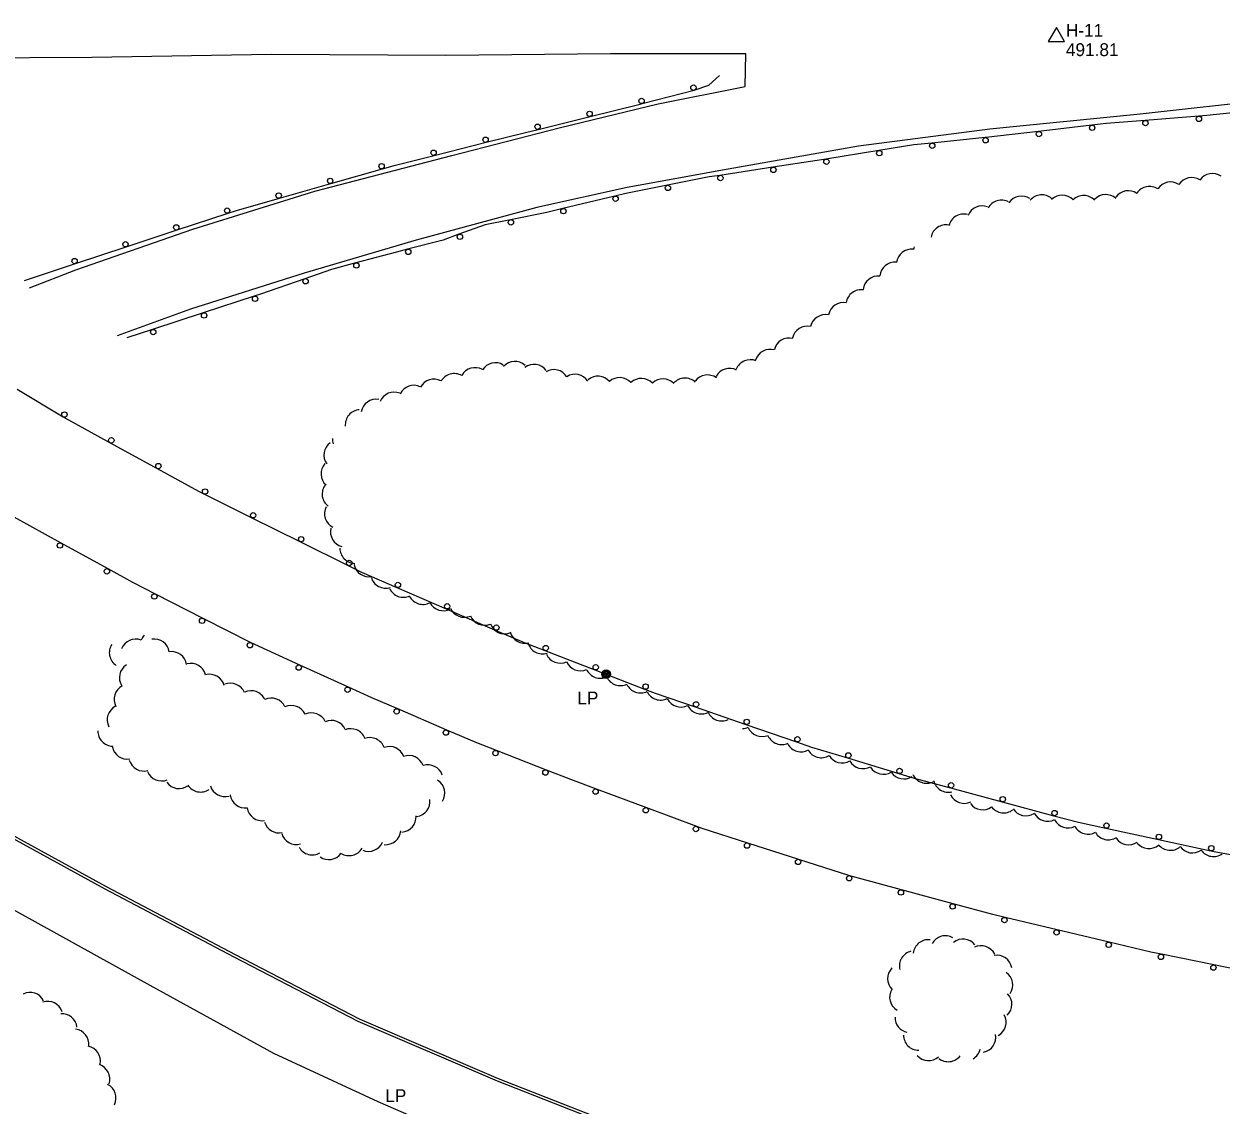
# Model space of a CAD drawing. Extents: x 2402803 to 2427059, y 6985292 to 6997652.
# Drawn here: x 2417273.9 to 2417720.3, y 6990965.6 to 6991368.8 of the extents above; entities that cross this region are included whole.
import ezdxf

# ---------------------------------------------------------------- set-up
doc = ezdxf.new("R2010")
doc.units = 0
for name, color, linetype in [('p_control ground ctrl', 7, 'Continuous'), ('p_road - paved curb', 7, 'Continuous'), ('p_road guard rails', 7, 'Continuous'), ('p_utility manhole', 7, 'Continuous'), ('p_veg woods', 7, 'Continuous'), ('V7 LEVEL 31', 7, 'Continuous')]:
    doc.layers.add(name, color=color, linetype=linetype)

msp = doc.modelspace()

# ---------------------------------------------------------------- linework, layer by layer
at = {"layer": 'p_control ground ctrl'}
for p, q in [((2417658.86, 6991367.48), (2417655.86, 6991362.28)), ((2417661.86, 6991362.28), (2417658.86, 6991367.48)), ((2417655.86, 6991362.28), (2417661.86, 6991362.28)), ((2417658.86, 6991364), (2417658.86, 6991364.04))]:
    msp.add_line(p, q, dxfattribs=at)
at = {"layer": 'p_road - paved curb'}
for points in [[(2417275.88, 6991270.34), (2417293.26, 6991277.04), (2417336.91, 6991292.21), (2417382.32, 6991306.42), (2417433.4, 6991319.71), (2417473.97, 6991330.18), (2417510.41, 6991338.96), (2417542.82, 6991345.45), (2417543.12, 6991357.69), (2417492.59, 6991357.71), (2417431.19, 6991357.03), (2417366.14, 6991357.43), (2417299.23, 6991356.3), (2417252.69, 6991356.08), (2417188.74, 6991355.17), (2417152.25, 6991354.93)], [(2418072.8, 6991352.05), (2418071.7, 6991352.04), (2418029.59, 6991351.13), (2417976.83, 6991352.21), (2417927.51, 6991351.28), (2417887.18, 6991349.28), (2417844.29, 6991346.03), (2417797.06, 6991344.87), (2417739.41, 6991340.6), (2417690.1, 6991335.1), (2417634, 6991329.56), (2417585.11, 6991323.22), (2417536.45, 6991314.6), (2417498.86, 6991307.78), (2417465.16, 6991300.29), (2417420.17, 6991288.13), (2417378.32, 6991275.91), (2417336.02, 6991262.39), (2417308.65, 6991252.45)], [(2417102.44, 6991155.35), (2417147.44, 6991131.02), (2417202.6, 6991101.41), (2417246.57, 6991077.7), (2417304.09, 6991046.19), (2417352.2, 6991020.88), (2417398.41, 6990996.87), (2417450.39, 6990974.63), (2417510.07, 6990951.19), (2417573, 6990930.87), (2417630.32, 6990916.28), (2417690.09, 6990903.9), (2417747.18, 6990895.52), (2417798.03, 6990890.45), (2417854.87, 6990887.91), (2417913.31, 6990887.8), (2417972.37, 6990890.82), (2418042.27, 6990897.81), (2418103.6, 6990905.73), (2418162.42, 6990914.12), (2418202.32, 6990920.88), (2418234.72, 6990926.56)], [(2417102.92, 6991156.23), (2417147.91, 6991131.9), (2417203.07, 6991102.29), (2417247.05, 6991078.58), (2417304.56, 6991047.07), (2417352.66, 6991021.77), (2417398.84, 6990997.77), (2417450.77, 6990975.56), (2417510.41, 6990952.13), (2417573.28, 6990931.83), (2417630.54, 6990917.25), (2417690.26, 6990904.89), (2417747.3, 6990896.51), (2417798.1, 6990891.45), (2417854.89, 6990888.91), (2417913.29, 6990888.8), (2417972.29, 6990891.82), (2418042.16, 6990898.8), (2418103.47, 6990906.72), (2418162.27, 6990915.11), (2418202.15, 6990921.87), (2418234.55, 6990927.54)], [(2417663.11, 6990894.16), (2417661.52, 6990884.87), (2417622.52, 6990891.62), (2417574.86, 6990904.07), (2417532.81, 6990916.94), (2417488.56, 6990932.5), (2417444.88, 6990949.85), (2417405.95, 6990966.76), (2417367, 6990984.85), (2417320.93, 6991010.25), (2417251.16, 6991048.68), (2417181.38, 6991084.69), (2417135.29, 6991109.88), (2417079.87, 6991140.57)]]:
    msp.add_lwpolyline(points, dxfattribs=at)
at = {"layer": 'p_road guard rails'}
for p, q in [((2417504.43, 6991339.11), (2417523.79, 6991344.06)), ((2417465.66, 6991329.49), (2417485.05, 6991334.3)), ((2417711.95, 6991334.39), (2417692.02, 6991332.83)), ((2417672.1, 6991331.06), (2417652.23, 6991328.74)), ((2417426.88, 6991319.79), (2417446.27, 6991324.65)), ((2417632.37, 6991326.41), (2417612.47, 6991324.38)), ((2417592.68, 6991321.59), (2417572.95, 6991318.42)), ((2417388.33, 6991309.31), (2417407.53, 6991314.78)), ((2417553.19, 6991315.37), (2417533.43, 6991312.34)), ((2417369.13, 6991303.84), (2417388.33, 6991309.31)), ((2417494.27, 6991304.59), (2417474.81, 6991299.95)), ((2417331, 6991291.96), (2417349.97, 6991298.24)), ((2417312.04, 6991285.69), (2417331, 6991291.96)), ((2417293.07, 6991279.41), (2417312.04, 6991285.69)), ((2417274.11, 6991273.14), (2417293.07, 6991279.41)), ((2417359.73, 6991267.25), (2417340.74, 6991261.04)), ((2417340.74, 6991261.04), (2417321.76, 6991254.83)), ((2417321.76, 6991254.83), (2417312.27, 6991251.73)), ((2417271.34, 6991232.6), (2417288.46, 6991222.27)), ((2417305.98, 6991212.63), (2417323.51, 6991203.03)), ((2417340.99, 6991193.55), (2417358.9, 6991184.66)), ((2417287.75, 6991175.17), (2417270.23, 6991184.8)), ((2417358.9, 6991184.66), (2417376.81, 6991175.77)), ((2417305.28, 6991165.54), (2417287.75, 6991175.17)), ((2417376.81, 6991175.77), (2417394.72, 6991166.88)), ((2417340.76, 6991147.09), (2417322.95, 6991156.17)), ((2417412.94, 6991158.66), (2417431.29, 6991150.71)), ((2417431.29, 6991150.71), (2417449.64, 6991142.75)), ((2417358.58, 6991138), (2417340.76, 6991147.09)), ((2417468.1, 6991135.12), (2417486.72, 6991127.94)), ((2417394.96, 6991121.43), (2417376.75, 6991129.68)), ((2417486.72, 6991127.94), (2417505.34, 6991120.76)), ((2417431.61, 6991105.44), (2417413.24, 6991113.35)), ((2417524.18, 6991114.1), (2417543.07, 6991107.59)), ((2417543.07, 6991107.59), (2417561.97, 6991101.08)), ((2417468.71, 6991090.55), (2417450.08, 6991097.79)), ((2417581.01, 6991095.06), (2417600.1, 6991089.25)), ((2417506.1, 6991076.47), (2417487.39, 6991083.45)), ((2417619.34, 6991083.89), (2417638.63, 6991078.71)), ((2417524.81, 6991069.5), (2417506.1, 6991076.47)), ((2417638.63, 6991078.71), (2417657.93, 6991073.53)), ((2417677.35, 6991068.86), (2417696.9, 6991064.65)), ((2417562.86, 6991057.23), (2417543.82, 6991063.32)), ((2417696.9, 6991064.65), (2417716.44, 6991060.44)), ((2417581.9, 6991051.14), (2417562.86, 6991057.23)), ((2417620.43, 6991040.64), (2417601.15, 6991045.85)), ((2417659.18, 6991030.96), (2417639.74, 6991035.57)), ((2417678.61, 6991026.34), (2417659.18, 6991030.96)), ((2417717.64, 6991017.85), (2417698.07, 6991021.85)), ((2417737.21, 6991013.86), (2417717.64, 6991017.85))]:
    msp.add_line(p, q, dxfattribs=at)
for points in [[(2417523.79, 6991344.06), (2417523.82, 6991344.07), (2417529.22, 6991345.97), (2417533.26, 6991349.51)], [(2417485.05, 6991334.3), (2417503.65, 6991338.91), (2417504.43, 6991339.11)], [(2417731.85, 6991336.39), (2417714.95, 6991334.63), (2417711.95, 6991334.39)], [(2417446.27, 6991324.65), (2417460.95, 6991328.32), (2417465.66, 6991329.49)], [(2417692.02, 6991332.83), (2417677.4, 6991331.68), (2417672.1, 6991331.06)], [(2417612.47, 6991324.38), (2417605.66, 6991323.68), (2417592.68, 6991321.59)], [(2417652.23, 6991328.74), (2417632.53, 6991326.43), (2417632.37, 6991326.41)], [(2417407.53, 6991314.78), (2417412.37, 6991316.16), (2417426.88, 6991319.79)], [(2417572.95, 6991318.42), (2417569.72, 6991317.9), (2417553.19, 6991315.37)], [(2417533.43, 6991312.34), (2417529.45, 6991311.73), (2417513.82, 6991308.63)], [(2417513.82, 6991308.63), (2417498.28, 6991305.54), (2417494.27, 6991304.59)], [(2417349.97, 6991298.24), (2417353.09, 6991299.27), (2417369.13, 6991303.84)], [(2417474.81, 6991299.95), (2417468.87, 6991298.54), (2417455.26, 6991295.79)], [(2417455.26, 6991295.79), (2417445.85, 6991293.89), (2417436.09, 6991290.34)], [(2417436.09, 6991290.34), (2417430.15, 6991288.18), (2417416.93, 6991284.76)], [(2417416.93, 6991284.76), (2417412.8, 6991283.69), (2417397.6, 6991279.67)], [(2417397.6, 6991279.67), (2417388.52, 6991277.27), (2417378.56, 6991273.78)], [(2417378.56, 6991273.78), (2417362.04, 6991268), (2417359.73, 6991267.25)], [(2417288.46, 6991222.27), (2417289.34, 6991221.74), (2417305.98, 6991212.63)], [(2417323.51, 6991203.03), (2417338.92, 6991194.6), (2417338.92, 6991194.57), (2417340.99, 6991193.55)], [(2417322.95, 6991156.17), (2417314.48, 6991160.49), (2417305.28, 6991165.54)], [(2417394.72, 6991166.88), (2417399.73, 6991164.39), (2417412.94, 6991158.66)], [(2417449.64, 6991142.75), (2417460.35, 6991138.11), (2417468.1, 6991135.12)], [(2417376.75, 6991129.68), (2417359.91, 6991137.32), (2417358.58, 6991138)], [(2417413.24, 6991113.35), (2417403.57, 6991117.52), (2417394.96, 6991121.43)], [(2417505.34, 6991120.76), (2417509.22, 6991119.26), (2417524.18, 6991114.1)], [(2417450.08, 6991097.79), (2417442.74, 6991100.64), (2417431.61, 6991105.44)], [(2417561.97, 6991101.08), (2417567.59, 6991099.14), (2417581.01, 6991095.06)], [(2417487.39, 6991083.45), (2417477.77, 6991087.03), (2417468.71, 6991090.55)], [(2417600.1, 6991089.25), (2417605.84, 6991087.51), (2417619.34, 6991083.89)], [(2417657.93, 6991073.53), (2417667.07, 6991071.08), (2417677.35, 6991068.86)], [(2417543.82, 6991063.32), (2417526.83, 6991068.75), (2417524.81, 6991069.5)], [(2417716.44, 6991060.44), (2417717.74, 6991060.16), (2417736.09, 6991056.79)], [(2417601.15, 6991045.85), (2417583.75, 6991050.55), (2417581.9, 6991051.14)], [(2417639.74, 6991035.57), (2417635.21, 6991036.65), (2417620.43, 6991040.64)], [(2417698.07, 6991021.85), (2417694.12, 6991022.66), (2417678.61, 6991026.34)]]:
    msp.add_lwpolyline(points, dxfattribs=at)
for centre in [(2417523.54, 6991345.03), (2417504.18, 6991340.08), (2417484.81, 6991335.27), (2417712.03, 6991333.4), (2417465.42, 6991330.46), (2417672.21, 6991330.07), (2417692.09, 6991331.83), (2417446.03, 6991325.62), (2417612.57, 6991323.38), (2417632.47, 6991325.42), (2417652.35, 6991327.74), (2417426.63, 6991320.76), (2417592.84, 6991320.61), (2417407.25, 6991315.74), (2417573.11, 6991317.43), (2417388.06, 6991310.27), (2417533.58, 6991311.35), (2417553.35, 6991314.38), (2417514.01, 6991307.65), (2417368.86, 6991304.8), (2417494.5, 6991303.61), (2417349.65, 6991299.19), (2417475.04, 6991298.98), (2417330.69, 6991292.91), (2417455.45, 6991294.81), (2417436.43, 6991289.4), (2417311.73, 6991286.64), (2417417.18, 6991283.79), (2417292.76, 6991280.36), (2417397.86, 6991278.71), (2417378.89, 6991272.84), (2417360.04, 6991266.3), (2417341.06, 6991260.09), (2417322.07, 6991253.88), (2417288.98, 6991223.13), (2417306.46, 6991213.51), (2417323.99, 6991203.91), (2417341.43, 6991194.44), (2417359.34, 6991185.55), (2417377.25, 6991176.66), (2417287.27, 6991174.29), (2417395.16, 6991167.77), (2417304.8, 6991164.66), (2417413.34, 6991159.58), (2417322.49, 6991155.28), (2417431.69, 6991151.62), (2417340.31, 6991146.19), (2417450.04, 6991143.67), (2417358.12, 6991137.11), (2417468.46, 6991136.05), (2417376.34, 6991128.77), (2417487.08, 6991128.87), (2417394.54, 6991120.52), (2417505.7, 6991121.69), (2417524.51, 6991115.05), (2417412.85, 6991112.43), (2417543.4, 6991108.54), (2417431.21, 6991104.52), (2417562.3, 6991102.02), (2417449.72, 6991096.86), (2417581.3, 6991096.02), (2417468.35, 6991089.62), (2417600.39, 6991090.21), (2417487.04, 6991082.51), (2417619.6, 6991084.85), (2417638.89, 6991079.68), (2417505.75, 6991075.54), (2417658.19, 6991074.5), (2417677.56, 6991069.84), (2417524.46, 6991068.57), (2417697.11, 6991065.63), (2417543.51, 6991062.37), (2417716.65, 6991061.42), (2417562.56, 6991056.28), (2417581.6, 6991050.19), (2417600.89, 6991044.88), (2417620.17, 6991039.68), (2417639.51, 6991034.6), (2417658.94, 6991029.99), (2417678.38, 6991025.37), (2417697.87, 6991020.87), (2417717.44, 6991016.87)]:
    msp.add_circle(centre, 1, dxfattribs=at)
at = {"layer": 'p_utility manhole'}
for radius in [1.6, 1.3, 1, 0.539, 0.192]:
    msp.add_circle((2417491.03, 6991126.28), radius, dxfattribs=at)
at = {"layer": 'p_veg woods'}
for centre, start, end in [((2417709.31, 6991305.87), 56.903, 146.903), ((2417717.07, 6991307.33), 55.4286, 145.4286), ((2417685.68, 6991300.96), 55.0374, 145.0374), ((2417693.62, 6991302.56), 56.4386, 146.4386), ((2417701.48, 6991304.22), 56.903, 146.903), ((2417638.42, 6991297.46), 61.9302, 151.9302), ((2417645.9, 6991298.95), 56.5986, 146.5986), ((2417653.39, 6991299.4), 49.2176, 139.2176), ((2417661.05, 6991299.26), 44.2685, 134.2685), ((2417669.06, 6991299.17), 44.4242, 134.4242), ((2417677.29, 6991299.53), 47.8034, 137.8034), ((2417624.3, 6991292.24), 75.3959, 165.3959), ((2417631.22, 6991295.32), 69.1231, 159.1231), ((2417617.69, 6991288.24), 79.2484, 169.2484), ((2417604.84, 6991279.14), 82.9066, 172.9066), ((2417611.2, 6991283.85), 161.5656, 171.6236), ((2417598.64, 6991274.28), 84.5701, 174.5701), ((2417592.45, 6991269.14), 83.9045, 173.9045), ((2417586.05, 6991264), 80.8571, 170.8571), ((2417579.45, 6991259.24), 78.8144, 168.8144), ((2417572.74, 6991254.75), 77.8002, 167.8002), ((2417566.01, 6991250.41), 77.6683, 167.6683), ((2417559.18, 6991246), 75.7371, 165.7371), ((2417552.13, 6991241.81), 72.9008, 162.9008), ((2417442.08, 6991234.98), 61.0508, 151.0507), ((2417449.65, 6991236.81), 58.0793, 148.0793), ((2417456.95, 6991237.28), 48.0542, 138.0542), ((2417464.13, 6991236.15), 37.1526, 127.1526), ((2417471.52, 6991234.24), 31.7164, 121.7164), ((2417536.98, 6991234.71), 62.2601, 152.2601), ((2417544.75, 6991237.94), 68.1706, 158.1706), ((2417426.76, 6991230.7), 62.4444, 152.4444), ((2417434.34, 6991232.76), 60.4241, 150.4241), ((2417479.41, 6991232.5), 32.826, 122.826), ((2417487.91, 6991231.79), 40.3516, 130.3516), ((2417495.98, 6991231.27), 41.5775, 131.5775), ((2417504.07, 6991230.95), 42.9485, 132.9485), ((2417512.15, 6991230.79), 44.1086, 134.1086), ((2417520.37, 6991231.07), 47.3426, 137.3426), ((2417528.72, 6991232.26), 53.4981, 143.4981), ((2417411.91, 6991225.84), 67.8133, 157.8133), ((2417419.26, 6991228.4), 64.7073, 154.7073), ((2417405.23, 6991223.19), 80.2793, 170.2793), ((2417399.33, 6991219.26), 94.1613, 184.1613), ((2417394.58, 6991213.94), 177.07, 197.2145), ((2417391.38, 6991208.02), 125.4372, 215.4372), ((2417390.29, 6991201.07), 138.009, 228.009), ((2417390.73, 6991193.46), 143.0587, 233.0587), ((2417391.6, 6991186.19), 153.3154, 243.3154), ((2417393.83, 6991179.37), 165.3944, 255.3944), ((2417397.33, 6991173.27), 179.8124, 269.8124), ((2417402.52, 6991168.26), 190.9636, 280.9636), ((2417408.75, 6991164.06), 197.2155, 287.2155), ((2417415.37, 6991160.62), 204.7678, 294.7678), ((2417422.67, 6991157.97), 207.6504, 297.6504), ((2417430.23, 6991155.62), 207.604, 297.604), ((2417438.09, 6991153.17), 203.4936, 293.4936), ((2417445.64, 6991150.18), 201.7733, 291.7733), ((2417453.11, 6991146.99), 200.0098, 290.0098), ((2417460.66, 6991143.5), 194.6975, 284.6975), ((2417311.35, 6991134.35), 147.2081, 237.2081), ((2417315.52, 6991133.73), 68.7132, 158.7132), ((2417322.84, 6991136.95), 136.8819, 158.7132), ((2417322.48, 6991133.76), 8.9866, 98.9866), ((2417467.28, 6991139.52), 196.9623, 286.9623), ((2417328.95, 6991129.06), 8.9866, 98.9866), ((2417473.91, 6991136.04), 203.8671, 293.8671), ((2417315.1, 6991125), 122.4184, 212.4184), ((2417336.11, 6991124.7), 14.4379, 104.4379), ((2417481.33, 6991133.2), 204.6176, 294.6176), ((2417488.81, 6991130.43), 204.9305, 294.9305), ((2417343.08, 6991120.61), 15.6355, 105.6355), ((2417496.32, 6991127.68), 205.0821, 295.0821), ((2417313.15, 6991116.91), 117.7351, 207.7351), ((2417350.87, 6991117.29), 22.3315, 112.3315), ((2417358.54, 6991114.5), 24.6012, 114.6012), ((2417503.8, 6991124.94), 205.5476, 295.5476), ((2417511.31, 6991122.28), 206.0094, 296.0094), ((2417366.07, 6991111.74), 24.7929, 114.7929), ((2417373.58, 6991108.98), 24.8877, 114.8877), ((2417518.86, 6991119.69), 206.2651, 296.265), ((2417526.45, 6991117.12), 206.023, 296.023), ((2417310.55, 6991109.3), 117.1205, 207.1205), ((2417381.1, 6991106.23), 24.8885, 114.8885), ((2417534.08, 6991114.51), 205.1249, 295.1249), ((2417388.51, 6991103.41), 23.9941, 113.9941), ((2417395.74, 6991100.32), 22.0318, 112.0318), ((2417541.72, 6991111.69), 271.6083, 293.0371), ((2417549.13, 6991108.69), 203.1094, 293.1094), ((2417307.05, 6991105.1), 179.2875, 269.2875), ((2417402.91, 6991096.99), 20.539, 110.539), ((2417556.44, 6991105.72), 204.7993, 294.7993), ((2417312.4, 6991100.24), 190.0925, 280.0925), ((2417410.18, 6991093.67), 20.4769, 110.4769), ((2417563.67, 6991102.99), 208.6798, 298.6798), ((2417571.21, 6991100.8), 210.7257, 300.7257), ((2417318.56, 6991095.82), 196.1264, 286.1264), ((2417417.4, 6991090.31), 19.9741, 109.9741), ((2417424.52, 6991086.85), 18.7439, 108.7439), ((2417579.03, 6991098.85), 209.9389, 299.9389), ((2417586.79, 6991096.73), 209.2809, 299.2809), ((2417325.18, 6991092.14), 202.4233, 292.4233), ((2417594.32, 6991094.61), 211.8578, 301.8578), ((2417602.05, 6991092.87), 212.9579, 302.9579), ((2417610.46, 6991091.29), 205.2696, 295.2696), ((2417331.72, 6991089.28), 215.4601, 305.4601), ((2417339.73, 6991088.01), 213.9048, 303.9048), ((2417348.86, 6991086.26), 196.4043, 286.4043), ((2417425.16, 6991081.92), 328.2238, 58.2238), ((2417618.6, 6991087.93), 193.6797, 283.6797), ((2417356.34, 6991082.07), 188.2448, 278.2448), ((2417419.63, 6991078.85), 277.2196, 7.2196), ((2417624.53, 6991083.76), 205.4612, 295.4612), ((2417362.7, 6991077.28), 188.8151, 278.8151), ((2417631.39, 6991081.37), 216.2863, 306.2863), ((2417639.23, 6991080.21), 217.3696, 307.3696), ((2417647.54, 6991079.13), 211.9843, 301.9843), ((2417655.64, 6991077.09), 207.017, 297.017), ((2417369.03, 6991072.76), 196.439, 282.019), ((2417414.47, 6991073.06), 273.6713, 3.6713), ((2417663.22, 6991074.62), 207.3579, 297.3579), ((2417375.44, 6991068.43), 195.9241, 285.9241), ((2417408.74, 6991068.35), 265.0306, 355.0306), ((2417670.69, 6991072.29), 209.8099, 299.8099), ((2417678.27, 6991070.18), 211.7416, 301.7416), ((2417381.42, 6991064.53), 209.8097, 299.8097), ((2417395.1, 6991064.28), 238.8971, 328.8971), ((2417402.39, 6991065.87), 247.005, 337.005), ((2417685.84, 6991068.31), 214.6959, 304.6959), ((2417693.37, 6991066.91), 219.7147, 309.7147), ((2417701.39, 6991066.27), 218.9732, 308.9732), ((2417709.6, 6991065.3), 215.2017, 305.2017), ((2417387.54, 6991062.79), 234.7058, 324.7058), ((2417717.48, 6991063.94), 215.2411, 305.2411), ((2417611.12, 6991021.64), 83.463, 173.463), ((2417617.51, 6991023.1), 60.4471, 150.4471), ((2417624.06, 6991021.88), 38.7618, 128.7618), ((2417605.97, 6991017.47), 103.6867, 193.6867), ((2417630.81, 6991019.38), 26.4655, 116.4655), ((2417636.65, 6991015.85), 9.9478, 99.9478), ((2417601.6, 6991012.82), 135.9366, 225.9366), ((2417636.98, 6991010.4), 325.6863, 55.6863), ((2417276.14, 6991001.97), 27.05, 117.05), ((2417602.34, 6991005.87), 149.8497, 239.8497), ((2417282.73, 6990998.65), 18.3029, 108.3029), ((2417636.65, 6991003.17), 314.1086, 44.1086), ((2417288.04, 6990994.02), 6.7296, 94.4728), ((2417634.49, 6990996.55), 298.297, 28.297), ((2417604.37, 6990998.26), 179.2377, 257.4267), ((2417292.43, 6990988.33), 353.1152, 83.1152), ((2417607.51, 6990991.73), 180.4021, 270.4021), ((2417630.64, 6990990.86), 281.3941, 11.3941), ((2417296.78, 6990981.96), 349.424, 79.424), ((2417624.95, 6990987.71), 300.7748, 347.149), ((2417300.24, 6990975.32), 342.0359, 72.0359), ((2417611.26, 6990987.85), 220.8292, 310.8292), ((2417618.51, 6990987.44), 231.6104, 321.6104), ((2417302.55, 6990968.28), 333.4764, 63.4764)]:
    msp.add_arc(centre, 5.65, start, end, dxfattribs=at)

# ---------------------------------------------------------------- texts
at = {"layer": 'p_control ground ctrl'}
msp.add_text('  H-11', height=4.8, dxfattribs=at).set_placement((2417658.86, 6991364))
at = {"layer": 'p_utility manhole'}
for p in [(2417476.68, 6991115.02), (2417405.05, 6990966.7)]:
    msp.add_text('  LP', height=4.8, dxfattribs=at).set_placement(p)
at = {"layer": 'V7 LEVEL 31'}
msp.add_text('  491.81', height=4.8, dxfattribs=at).set_placement((2417658.86, 6991356.8))

doc.saveas('drawing.dxf')
